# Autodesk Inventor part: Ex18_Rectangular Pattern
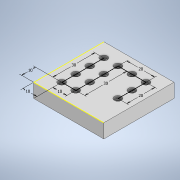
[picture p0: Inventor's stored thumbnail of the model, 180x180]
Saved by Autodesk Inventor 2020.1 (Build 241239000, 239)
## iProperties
Created: 2019-11
Part Number: Ex18_Rectangular Pattern
Material: Generic
Document SubType Name: Modeling
Designer: Synergysoft Dell02
Density: 1 g/cm^3
Appearance: Default
Author: Synergysoft Dell02
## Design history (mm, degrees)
sketch "Sketch1"
  geometry: L1 (0, 0)-(50, 0); L2 (50, 0)-(50, -50); L3 (50, -50)-(0, -50); L4 (0, -50)-(0, 0)
  constraints: 8 end point, 2 parallel, 1 horizontal, 1 perpendicular
  dimensions: "d0" = 50 distance of L2.end L3.end; "d1" = 50 distance of L1.end L2.end
extrude "Extrusion1" new body sketch "Sketch1" distance "d2" = 10; taper "d3" = 0 deg
sketch "Sketch3"
  geometry: L1 (-40, 40)-(-40, 10); L2 (-40, 10)-(-30, 10); L3 (-30, 10)-(-30, 40); L4 (-30, 40)-(-10, 40); L5 (-10, 40)-(-10, 20); L6 (-50, 50)-(-50, 0) reference; L7 (-50, 0)-(0, 0) reference
  constraints: 10 end point, 4 perpendicular, 1 vertical
  dimensions: "d19" = 30 distance of L1.start L1.end; "d20" = 10 distance of L1.end L2.end; "d21" = 30 distance of L2.end L3.end; "d22" = 20 distance of L3.end L4.end; "d23" = 20 distance of L4.end L5.end; "d24" = 10 distance between parallel lines of L1 L6; "d25" = 10 distance between parallel lines of L7 L2
hole "Hole2" sketch "Sketch3" diameter "d26" = 3; stored, may be unused: countersink angle "d30" = 90 deg, drill point angle "d32" = 118 deg; dims "d27" = 6, "d28" = 5, "d29" = 2, "d31" = 8
pattern_linear "Rectangular Pattern2"
sketch "Sketch2"
  geometry: L1 (-50, 0)-(0, 0) reference; L2 (0, 0)-(0, 50) reference; 1 further point
  dimensions: "d4" = 10 distance from line of L1 point (-10, 10); "d5" = 10 distance from line of L2 point (-10, 10)
hole "Hole1" sketch "Sketch2" at (-10, 10) diameter "d6" = 3; stored, may be unused: countersink angle "d10" = 90 deg, drill point angle "d12" = 118 deg; dims "d7" = 6, "d8" = 5, "d9" = 2, "d11" = 8
pattern_linear "Rectangular Pattern1" dims "d15" = 10, "d18" = 10
body "Solid1"
